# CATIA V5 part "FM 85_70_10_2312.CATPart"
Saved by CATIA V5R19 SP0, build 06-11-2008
Part number: FM 85_70_10_2312
Definition: FM 85_70_10_2312
Nomenclature: FM 85_70_10_2312
Source: Unknown
Description: PART--DESC
Bounding box of the stored display mesh (mm): x -35 to 35, y -35 to 35, z -50 to -40
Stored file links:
  C:\Users\jsmid\Desktop\DP_Smidak_Forma LEGO\FM 85_70_10_2312.CATPart
  C:\Users\jsmid\Desktop\Forma_kostka\FM 80_70_10_2312.3.CATPart
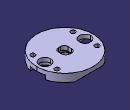
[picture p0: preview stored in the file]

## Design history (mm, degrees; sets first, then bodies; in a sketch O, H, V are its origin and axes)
Body1 "FM 85_70_10_2312" (main body)
  Solid1: solid without history
  DatumCurve1 to DatumCurve3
